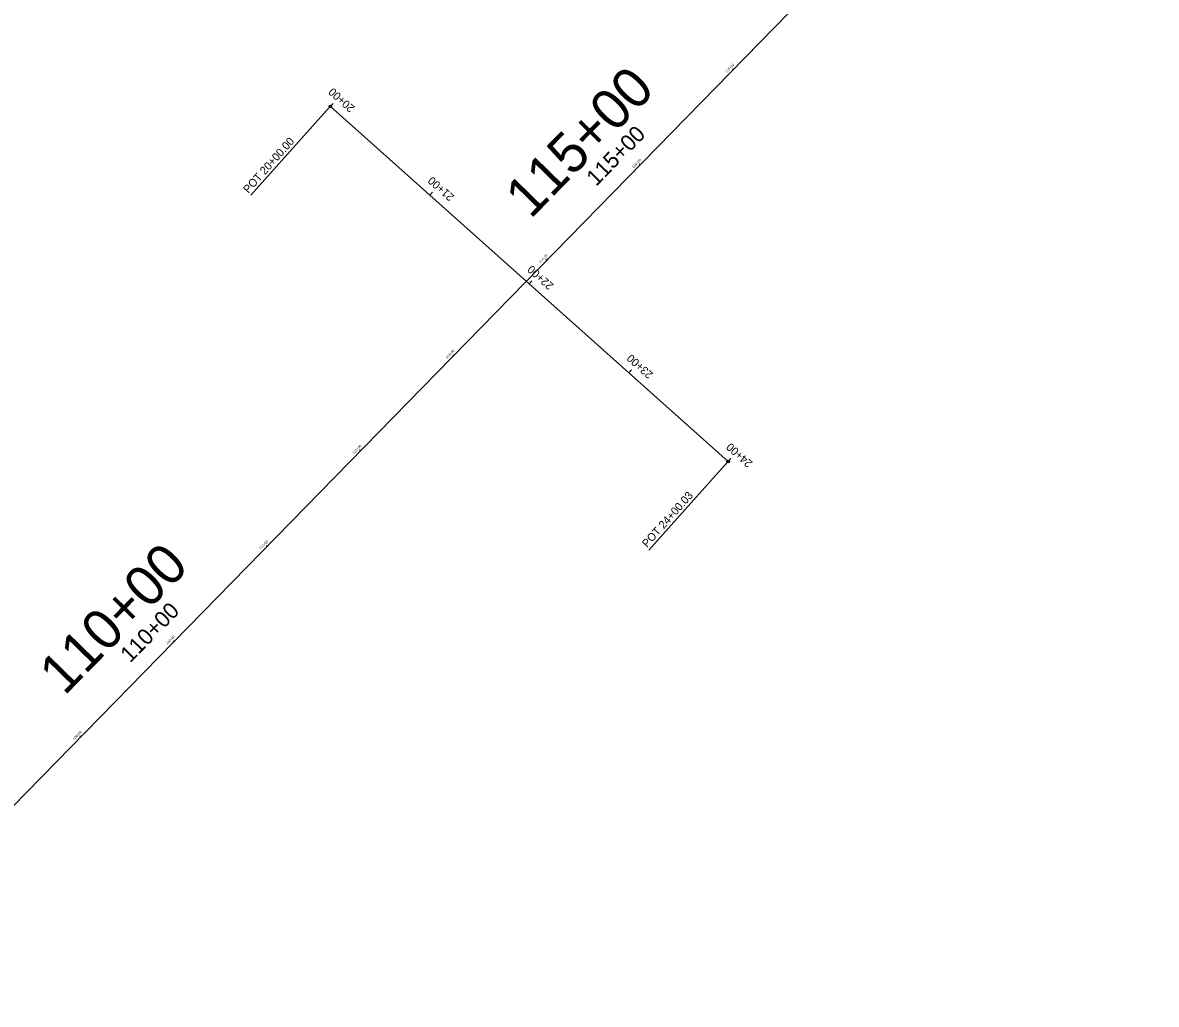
# Model space of a CAD drawing. Extents: x 2252491 to 2257126, y 13788370 to 13792743.
# Drawn here: x 2253250 to 2254100, y 13788919 to 13789656 of the extents above; entities that cross this region are included whole.
import ezdxf

# ---------------------------------------------------------------- set-up
doc = ezdxf.new("R2010")
doc.units = 0
for name, color, linetype in [('D_ALIGN_1', 7, 'Continuous'), ('D_ALIGN_ANNO_1', 7, 'Continuous'), ('D_ALIGN_ANNO_200_drn', 7, 'Continuous'), ('D_ALIGN_ANNO_DRN_300', 7, 'Continuous'), ('D_ALIGN_ANNO_RANCH_ESTATES', 7, 'Continuous'), ('D_ALIGN_RANCH_ESTATES', 7, 'Continuous')]:
    doc.layers.add(name, color=color, linetype=linetype)

msp = doc.modelspace()

# ---------------------------------------------------------------- linework, layer by layer
at = {"layer": 'D_ALIGN_1'}
msp.add_line((2253097.12, 13788919.23), (2254099.77, 13789945.21), dxfattribs=at)
at = {"layer": 'D_ALIGN_ANNO_1'}
for p, q in [((2253782.47, 13789620.53), (2253781.83, 13789621.16)), ((2253712.58, 13789549.01), (2253711.94, 13789549.64)), ((2253642.69, 13789477.49), (2253642.04, 13789478.12)), ((2253572.8, 13789405.97), (2253572.15, 13789406.6)), ((2253502.9, 13789334.45), (2253502.26, 13789335.08)), ((2253433.01, 13789262.93), (2253432.37, 13789263.56)), ((2253363.12, 13789191.42), (2253362.47, 13789192.04)), ((2253293.22, 13789119.9), (2253292.58, 13789120.53))]:
    msp.add_line(p, q, dxfattribs=at)
at = {"layer": 'D_ALIGN_ANNO_RANCH_ESTATES'}
for p, q in [((2253420.81, 13789526.33), (2253479.71, 13789592.27)), ((2253480.38, 13789593.01), (2253482.38, 13789595.25)), ((2253554.96, 13789526.39), (2253556.95, 13789528.63)), ((2253629.53, 13789459.78), (2253631.53, 13789462.01)), ((2253704.11, 13789393.16), (2253706.11, 13789395.39)), ((2253778.69, 13789326.54), (2253780.69, 13789328.77)), ((2253719.26, 13789260), (2253778.02, 13789325.79))]:
    msp.add_line(p, q, dxfattribs=at)
for centre in [(2253480.38, 13789593.01), (2253778.71, 13789326.52)]:
    msp.add_circle(centre, 1, dxfattribs=at)
at = {"layer": 'D_ALIGN_RANCH_ESTATES'}
for p, q in [((2253480.38, 13789593.01), (2253629.55, 13789459.76)), ((2253629.55, 13789459.76), (2253778.71, 13789326.52))]:
    msp.add_line(p, q, dxfattribs=at)

# ---------------------------------------------------------------- texts
at = {"layer": 'D_ALIGN_ANNO_1'}
for s, p in [('116+00', (2253777.55, 13789618.06)), ('115+00', (2253707.65, 13789546.54)), ('114+00', (2253637.76, 13789475.03)), ('113+00', (2253567.87, 13789403.51)), ('112+00', (2253497.98, 13789331.99)), ('111+00', (2253428.08, 13789260.47)), ('110+00', (2253358.19, 13789188.95)), ('109+00', (2253288.3, 13789117.43))]:
    msp.add_text(s, height=1.8, rotation=45.65877, dxfattribs=at).set_placement(p)
at = {"layer": 'D_ALIGN_ANNO_200_drn'}
for s, p in [('115+00', (2253679.74, 13789532.57)), ('110+00', (2253330.27, 13789174.98))]:
    msp.add_text(s, height=12, rotation=45.65877, dxfattribs=at).set_placement(p)
at = {"layer": 'D_ALIGN_ANNO_DRN_300'}
for s, p in [('115+00', (2253630.47, 13789507.91)), ('110+00', (2253281, 13789150.31))]:
    msp.add_text(s, height=30, rotation=45.65877, dxfattribs=at).set_placement(p)
at = {"layer": 'D_ALIGN_ANNO_RANCH_ESTATES'}
for s, rotation, p in [('20+00', 138.22648, (2253499.1, 13789592.38)), ('POT 20+00.00', 48.22648, (2253418.87, 13789527.35)), ('21+00', 138.22648, (2253573.68, 13789525.76)), ('22+00', 138.22648, (2253648.25, 13789459.14)), ('23+00', 138.22648, (2253722.83, 13789392.52)), ('24+00', 138.22648, (2253797.41, 13789325.91)), ('POT 24+00.03', 48.22648, (2253717.91, 13789261.62))]:
    msp.add_text(s, height=6, rotation=rotation, dxfattribs=at).set_placement(p)

doc.saveas('drawing.dxf')
